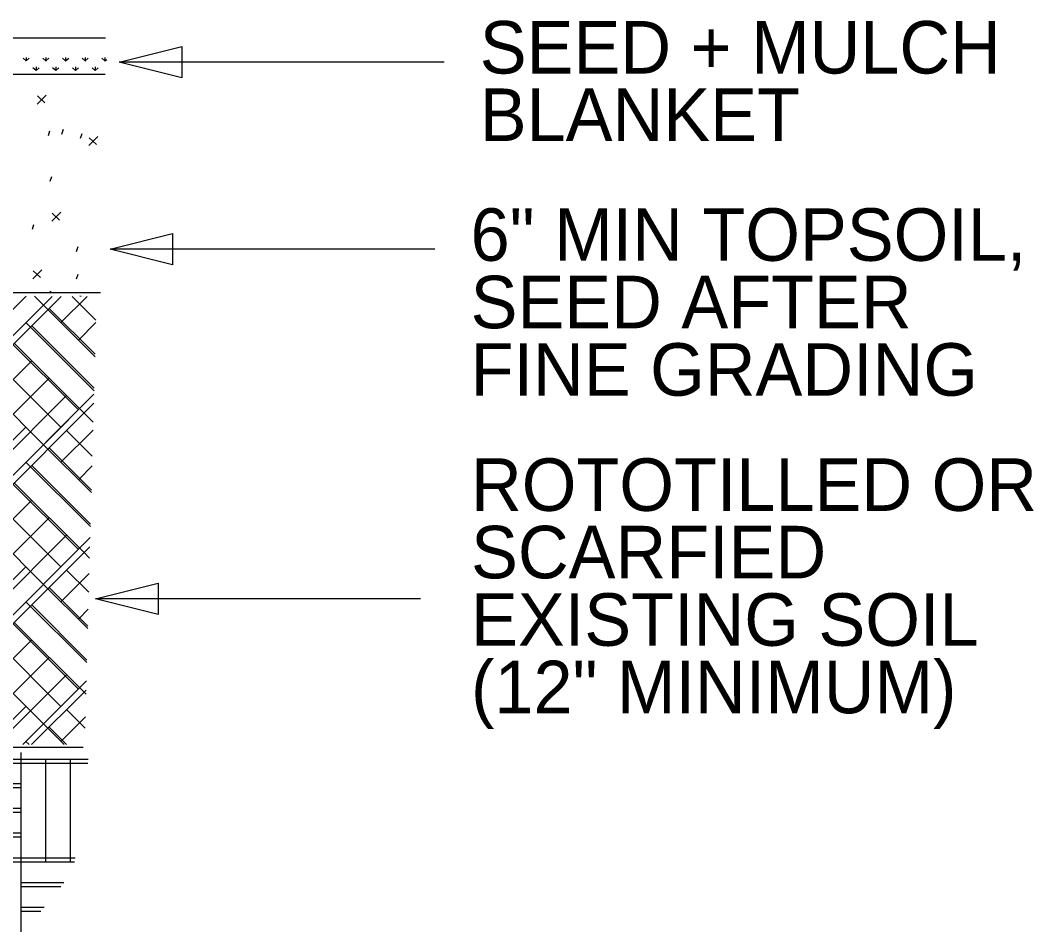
# Model space of a CAD drawing. Extents: x 9915.7 to 9955.7, y 9888.6 to 9936.3.
# Drawn here: x 9942.16 to 9955.67, y 9921.08 to 9933.23 of the extents above; entities that cross this region are included whole.
import ezdxf

# ---------------------------------------------------------------- set-up
doc = ezdxf.new("R2010")
doc.units = 0
for name, color, linetype in [('Default', 7, 'Continuous'), ('G-ANNO-TEXT', 7, 'Continuous'), ('G-ANNO-TTXT', 7, 'Continuous'), ('G-DETL-LINE', 7, 'Continuous'), ('G-DETL-PATT', 7, 'Continuous'), ('L-PLNT-SEED', 7, 'Continuous')]:
    doc.layers.add(name, color=color, linetype=linetype)

# ---------------------------------------------------------------- blocks, each defined once
blk = doc.blocks.new('TERARR')
at = {"layer": 'Default'}
blk.add_lwpolyline([(-0.667, 0.167), (0, 0), (-0.667, -0.167)], close=True, dxfattribs=at)

msp = doc.modelspace()

# ---------------------------------------------------------------- linework, layer by layer
at = {"layer": 'Default'}
for p, q in [((9942.553, 9929.616), (9942.57, 9929.612)), ((9942.954, 9929.555), (9942.971, 9929.551)), ((9942.172, 9923.05), (9940.856, 9923.05))]:
    msp.add_line(p, q, dxfattribs=at)
at = {"layer": 'G-ANNO-TEXT'}
for p, q in [((9947.807, 9932.669), (9943.478, 9932.669)), ((9947.684, 9930.176), (9943.356, 9930.176)), ((9947.492, 9925.516), (9943.163, 9925.516))]:
    msp.add_line(p, q, dxfattribs=at)
at = {"layer": 'G-ANNO-TTXT'}
msp.add_line((9926.737, 9932.993), (9943.294, 9932.993), dxfattribs=at)
at = {"layer": 'G-DETL-LINE'}
for p, q in [((9926.737, 9932.508), (9943.291, 9932.508)), ((9926.737, 9929.597), (9943.23, 9929.597)), ((9926.737, 9923.539), (9942.996, 9923.539))]:
    msp.add_line(p, q, dxfattribs=at)
at = {"layer": 'G-DETL-PATT'}
for p, q in [((9942.385, 9932.11), (9942.505, 9932.23)), ((9942.488, 9932.127), (9942.388, 9932.217)), ((9942.535, 9931.689), (9942.556, 9931.753)), ((9942.714, 9931.71), (9942.735, 9931.773)), ((9942.964, 9931.653), (9942.985, 9931.716)), ((9943.073, 9931.555), (9943.193, 9931.675)), ((9943.176, 9931.572), (9943.076, 9931.661)), ((9942.56, 9931.083), (9942.581, 9931.146)), ((9942.58, 9930.547), (9942.7, 9930.667)), ((9942.683, 9930.564), (9942.583, 9930.653)), ((9942.321, 9930.44), (9942.342, 9930.503)), ((9942.909, 9930.146), (9942.93, 9930.209)), ((9942.328, 9929.78), (9942.448, 9929.9)), ((9942.431, 9929.797), (9942.331, 9929.886)), ((9942.909, 9929.778), (9942.93, 9929.842)), ((9936.593, 9923.553), (9942.586, 9929.546)), ((9936.712, 9923.554), (9942.704, 9929.545)), ((9942.24, 9929.547), (9941.847, 9929.154)), ((9942.469, 9929.429), (9942.351, 9929.547)), ((9943.156, 9928.742), (9942.469, 9929.429)), ((9943.05, 9929.544), (9942.701, 9929.196)), ((9943.168, 9929.227), (9942.851, 9929.545)), ((9943.157, 9928.774), (9942.544, 9929.386)), ((9943.144, 9928.289), (9942.236, 9929.196)), ((9943.144, 9928.321), (9942.312, 9929.154)), ((9943.168, 9929.197), (9942.934, 9928.964)), ((9942.934, 9928.034), (9942.004, 9928.964)), ((9943.01, 9927.991), (9942.079, 9928.921)), ((9941.382, 9927.759), (9942.312, 9928.689)), ((9942.701, 9927.801), (9941.771, 9928.731)), ((9942.469, 9927.568), (9941.539, 9928.499)), ((9941.614, 9927.526), (9942.544, 9928.456)), ((9938.46, 9923.559), (9943.142, 9928.242)), ((9941.847, 9927.294), (9942.777, 9928.224)), ((9942.469, 9927.568), (9943.142, 9928.242)), ((9938.578, 9923.56), (9943.139, 9928.121)), ((9943.132, 9927.868), (9943.01, 9927.991)), ((9942.236, 9927.801), (9941.306, 9926.871)), ((9942.701, 9927.336), (9943.13, 9927.764)), ((9943.12, 9927.415), (9942.777, 9927.759)), ((9943.108, 9926.93), (9942.469, 9927.568)), ((9943.108, 9926.962), (9942.544, 9927.526)), ((9943.096, 9926.477), (9942.236, 9927.336)), ((9943.096, 9926.509), (9942.312, 9927.294)), ((9942.934, 9927.103), (9943.117, 9927.286)), ((9942.934, 9926.173), (9942.004, 9927.103)), ((9943.01, 9926.131), (9942.079, 9927.061)), ((9942.701, 9925.941), (9941.771, 9926.871)), ((9942.312, 9926.828), (9941.382, 9925.898)), ((9942.469, 9925.708), (9941.539, 9926.638)), ((9942.544, 9926.596), (9941.614, 9925.666)), ((9940.326, 9923.565), (9943.092, 9926.331)), ((9942.777, 9926.363), (9941.847, 9925.433)), ((9940.445, 9923.566), (9943.088, 9926.21)), ((9943.01, 9926.131), (9943.088, 9926.21)), ((9943.084, 9926.056), (9943.01, 9926.131)), ((9941.306, 9925.01), (9942.236, 9925.941)), ((9943.079, 9925.853), (9942.701, 9925.476)), ((9943.072, 9925.603), (9942.777, 9925.898)), ((9943.059, 9925.118), (9942.469, 9925.708)), ((9943.06, 9925.15), (9942.544, 9925.666)), ((9943.047, 9924.665), (9942.236, 9925.476)), ((9943.048, 9924.697), (9942.312, 9925.433)), ((9943.066, 9925.375), (9942.934, 9925.243)), ((9942.934, 9924.313), (9942.004, 9925.243)), ((9943.01, 9924.27), (9942.079, 9925.201)), ((9941.382, 9924.038), (9942.312, 9924.968)), ((9942.701, 9924.08), (9941.771, 9925.01)), ((9942.469, 9923.848), (9941.539, 9924.778)), ((9941.614, 9923.805), (9942.544, 9924.735)), ((9941.847, 9923.573), (9942.777, 9924.503)), ((9942.193, 9923.572), (9943.041, 9924.42)), ((9942.469, 9923.848), (9943.041, 9924.42)), ((9942.311, 9923.572), (9943.038, 9924.299)), ((9943.036, 9924.244), (9943.01, 9924.27)), ((9942.236, 9924.08), (9941.726, 9923.57)), ((9943.024, 9923.791), (9942.777, 9924.038)), ((9942.701, 9923.615), (9943.028, 9923.942)), ((9942.743, 9923.573), (9942.469, 9923.848)), ((9942.776, 9923.573), (9942.544, 9923.805)), ((9942.28, 9923.572), (9942.236, 9923.615)), ((9942.313, 9923.572), (9942.312, 9923.573)), ((9922.786, 9923.379), (9943.064, 9923.379)), ((9942.172, 9923.379), (9942.172, 9923.466)), ((9942.172, 9923.326), (9942.172, 9923.466)), ((9942.172, 9922.063), (9942.172, 9923.379)), ((9942.501, 9922.063), (9942.501, 9923.379)), ((9942.829, 9922.063), (9942.829, 9923.379)), ((9922.826, 9923.326), (9943.06, 9923.326)), ((9942.172, 9922.01), (9942.172, 9923.326)), ((9942.501, 9922.01), (9942.501, 9923.326)), ((9942.829, 9922.01), (9942.829, 9923.326)), ((9942.172, 9922.997), (9940.856, 9922.997)), ((9942.172, 9922.721), (9940.856, 9922.721)), ((9942.172, 9922.668), (9940.856, 9922.668)), ((9942.172, 9922.392), (9940.856, 9922.392)), ((9942.172, 9922.339), (9940.856, 9922.339)), ((9923.791, 9922.063), (9942.892, 9922.063)), ((9923.831, 9922.01), (9942.882, 9922.01)), ((9942.172, 9921.078), (9942.172, 9922.063)), ((9942.172, 9922.063), (9942.892, 9922.063)), ((9942.172, 9921.078), (9942.172, 9922.01)), ((9942.172, 9922.01), (9942.882, 9922.01)), ((9942.172, 9921.734), (9942.741, 9921.734)), ((9942.172, 9921.681), (9942.699, 9921.681)), ((9942.172, 9921.405), (9942.478, 9921.405)), ((9942.172, 9921.353), (9942.436, 9921.353))]:
    msp.add_line(p, q, dxfattribs=at)
at = {"layer": 'L-PLNT-SEED'}
for p, q in [((9942.239, 9932.687), (9942.198, 9932.72)), ((9942.239, 9932.685), (9942.237, 9932.687)), ((9942.239, 9932.731), (9942.239, 9932.687)), ((9942.239, 9932.687), (9942.28, 9932.72)), ((9942.239, 9932.685), (9942.24, 9932.687)), ((9942.239, 9932.687), (9942.239, 9932.685)), ((9942.501, 9932.687), (9942.46, 9932.72)), ((9942.501, 9932.685), (9942.5, 9932.687)), ((9942.501, 9932.731), (9942.501, 9932.687)), ((9942.501, 9932.687), (9942.542, 9932.72)), ((9942.501, 9932.685), (9942.503, 9932.687)), ((9942.501, 9932.687), (9942.501, 9932.685)), ((9942.764, 9932.687), (9942.723, 9932.72)), ((9942.764, 9932.685), (9942.762, 9932.687)), ((9942.764, 9932.731), (9942.764, 9932.687)), ((9942.764, 9932.687), (9942.805, 9932.72)), ((9942.764, 9932.685), (9942.765, 9932.687)), ((9942.764, 9932.687), (9942.764, 9932.685)), ((9943.026, 9932.687), (9942.985, 9932.72)), ((9943.026, 9932.685), (9943.025, 9932.687)), ((9943.026, 9932.731), (9943.026, 9932.687)), ((9943.026, 9932.687), (9943.067, 9932.72)), ((9943.026, 9932.685), (9943.028, 9932.687)), ((9943.026, 9932.687), (9943.026, 9932.685)), ((9943.289, 9932.687), (9943.248, 9932.72)), ((9943.289, 9932.685), (9943.287, 9932.687)), ((9943.289, 9932.731), (9943.289, 9932.687)), ((9943.289, 9932.687), (9943.312, 9932.705)), ((9943.289, 9932.685), (9943.29, 9932.687)), ((9943.289, 9932.687), (9943.289, 9932.685)), ((9942.37, 9932.558), (9942.329, 9932.591)), ((9942.37, 9932.607), (9942.37, 9932.558)), ((9942.37, 9932.558), (9942.411, 9932.591)), ((9942.632, 9932.558), (9942.591, 9932.591)), ((9942.632, 9932.607), (9942.632, 9932.558)), ((9942.632, 9932.558), (9942.673, 9932.591)), ((9942.895, 9932.558), (9942.854, 9932.591)), ((9942.895, 9932.607), (9942.895, 9932.558)), ((9942.895, 9932.558), (9942.936, 9932.591)), ((9943.157, 9932.558), (9943.116, 9932.591)), ((9943.157, 9932.607), (9943.157, 9932.558)), ((9943.157, 9932.558), (9943.198, 9932.591))]:
    msp.add_line(p, q, dxfattribs=at)

# ---------------------------------------------------------------- block references
at = {"layer": 'G-ANNO-TEXT', "xscale": 1.24992, "yscale": 1.24992, "rotation": 180}
for p in [(9943.478, 9932.669), (9943.356, 9930.176), (9943.163, 9925.516)]:
    msp.add_blockref('TERARR', p, dxfattribs=at)

# ---------------------------------------------------------------- texts
at = {"layer": 'G-ANNO-TEXT'}
for s, p in [('SEED + MULCH ', (9948.283, 9932.516)), ('BLANKET', (9948.283, 9931.617)), ('6" MIN TOPSOIL, ', (9948.161, 9930.02)), ('SEED AFTER ', (9948.161, 9929.121)), ('FINE GRADING', (9948.161, 9928.222)), ('ROTOTILLED OR', (9948.167, 9926.687)), ('SCARFIED ', (9948.167, 9925.788)), ('EXISTING SOIL ', (9948.167, 9924.889)), ('(12" MINIMUM)', (9948.167, 9923.99))]:
    msp.add_text(s, height=0.7, dxfattribs=at).set_placement(p)

doc.saveas('drawing.dxf')
